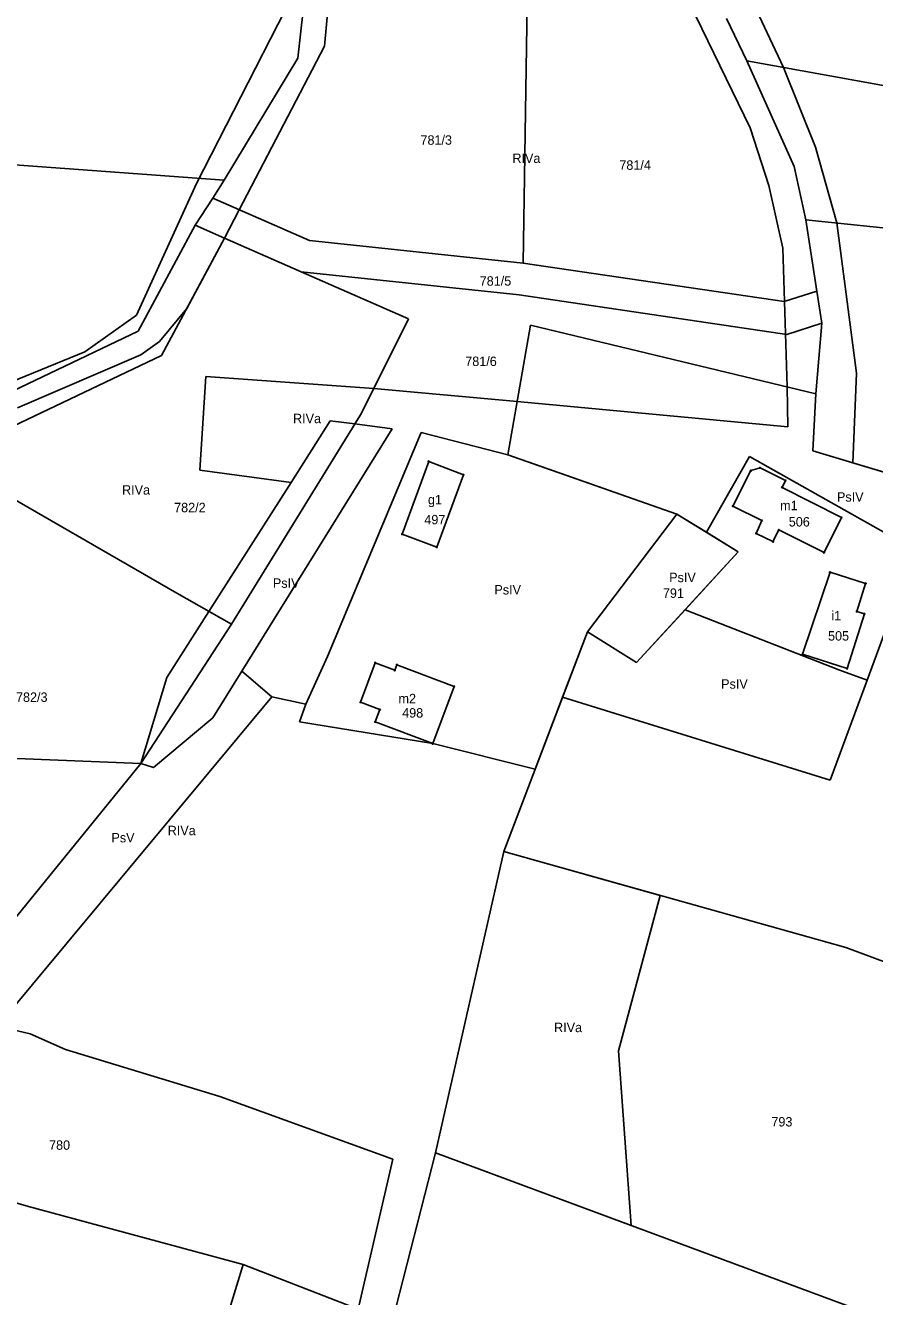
# Model space of a CAD drawing. Extents: x 7498273 to 7499989, y 5499795 to 5500810.
# Drawn here: x 7499281.1 to 7499416.3, y 5500492.7 to 5500695.1 of the extents above; entities that cross this region are included whole.
import ezdxf

# ---------------------------------------------------------------- set-up
doc = ezdxf.new("R2010")
doc.units = 0
for name, color, linetype in [('209-oznaczenie konturu klasyfikacyjnego', 7, 'Continuous'), ('211-numer działki ewidencyjnej', 7, 'Continuous'), ('217-kontur klasyfikacyjny', 7, 'Continuous'), ('218-kontur użytku gruntowego', 7, 'Continuous'), ('219-działka ewidencyjna', 7, 'Continuous'), ('312-budynek ewidencyjny', 7, 'Continuous'), ('312-oznaczenie budynku ewidencyjnego', 7, 'Continuous'), ('312-oznaczenie budynku ewidencyjnego-Atr117', 7, 'Continuous'), ('Punkt budynku', 7, 'Continuous')]:
    doc.layers.add(name, color=color, linetype=linetype)

# ---------------------------------------------------------------- blocks, each defined once
blk = doc.blocks.new('PUNKTBUD')
blk.add_circle((0, 0), 0.09)

msp = doc.modelspace()

# ---------------------------------------------------------------- linework, layer by layer
at = {"layer": '217-kontur klasyfikacyjny'}
for points in [[(7499328.67, 5500691.79), (7499329.52, 5500701.06)], [(7499396.99, 5500698.54), (7499401.78, 5500688.44)], [(7499308.33, 5500669.97), (7499322.43, 5500697.56)], [(7499396.43, 5500678.79), (7499387.8, 5500696.57)], [(7499315.13, 5500665.78), (7499328.67, 5500691.79)], [(7499401.78, 5500688.44), (7499406.83, 5500675.75)], [(7499399.44, 5500669.62), (7499396.43, 5500678.79)], [(7499406.83, 5500675.75), (7499410.25, 5500663.66)], [(7499298.78, 5500648.98), (7499308.33, 5500669.97)], [(7499401.63, 5500659.63), (7499399.44, 5500669.62)], [(7499312.78, 5500661.23), (7499315.13, 5500665.78)], [(7499410.25, 5500663.66), (7499413.39, 5500639.73)], [(7499306.77, 5500650.07), (7499312.78, 5500661.23)], [(7499325, 5500655.88), (7499312.78, 5500661.23)], [(7499402.35, 5500637.55), (7499401.63, 5500659.63)], [(7499342.09, 5500648.38), (7499325, 5500655.88)], [(7499302.41, 5500644.78), (7499306.77, 5500650.07)], [(7499290.56, 5500643.13), (7499298.78, 5500648.98)], [(7499336.54, 5500637.33), (7499342.09, 5500648.38)], [(7499299.44, 5500642.68), (7499302.41, 5500644.78)], [(7499267.15, 5500633.61), (7499290.56, 5500643.13)], [(7499279.82, 5500634.24), (7499299.44, 5500642.68)], [(7499413.39, 5500639.73), (7499412.78, 5500625.5)], [(7499308.83, 5500624.33), (7499309.83, 5500639.23)], [(7499309.83, 5500639.23), (7499336.54, 5500637.33)], [(7499402.44, 5500631.22), (7499402.35, 5500637.55)], [(7499334.43, 5500633.13), (7499336.54, 5500637.33)], [(7499336.54, 5500637.33), (7499359.35, 5500635.23)], [(7499359.35, 5500635.23), (7499402.44, 5500631.22)], [(7499329.61, 5500632.16), (7499323.38, 5500622.35)], [(7499333.52, 5500631.67), (7499329.61, 5500632.16)], [(7499333.52, 5500631.67), (7499334.43, 5500633.13)], [(7499339.48, 5500630.91), (7499333.52, 5500631.67)], [(7499315.52, 5500592.3), (7499339.48, 5500630.91)], [(7499329.16, 5500594.65), (7499344.06, 5500630.33)], [(7499344.06, 5500630.33), (7499357.87, 5500626.74)], [(7499357.87, 5500626.74), (7499364.22, 5500624.51)], [(7499389.5, 5500614.42), (7499396.35, 5500626.47)], [(7499396.35, 5500626.47), (7499422.72, 5500611.61)], [(7499412.78, 5500625.5), (7499426.35, 5500621.42)], [(7499323.38, 5500622.35), (7499308.83, 5500624.33)], [(7499364.22, 5500624.51), (7499384.77, 5500617.29)], [(7499310.3, 5500601.83), (7499323.38, 5500622.35)], [(7499370.57, 5500598.58), (7499384.77, 5500617.29)], [(7499384.77, 5500617.29), (7499389.5, 5500614.42)], [(7499394.54, 5500611.31), (7499389.5, 5500614.42)], [(7499386.1, 5500602.1), (7499394.54, 5500611.31)], [(7499422.72, 5500611.61), (7499415.06, 5500590.87)], [(7499303.6, 5500591.29), (7499310.3, 5500601.83)], [(7499386.1, 5500602.1), (7499378.37, 5500593.67)], [(7499410.58, 5500592.5), (7499386.1, 5500602.1)], [(7499366.6, 5500588.18), (7499370.57, 5500598.58)], [(7499378.37, 5500593.67), (7499370.57, 5500598.58)], [(7499325.71, 5500587.05), (7499329.16, 5500594.65)], [(7499299.48, 5500577.61), (7499303.6, 5500591.29)], [(7499315.52, 5500592.3), (7499310.92, 5500584.9)], [(7499320.32, 5500588.2), (7499315.52, 5500592.3)], [(7499415.06, 5500590.87), (7499409.17, 5500574.93)], [(7499415.06, 5500590.87), (7499410.58, 5500592.5)], [(7499320.32, 5500588.2), (7499276.67, 5500535.79)], [(7499325.71, 5500587.05), (7499320.32, 5500588.2)], [(7499324.71, 5500584.22), (7499325.71, 5500587.05)], [(7499366.6, 5500588.18), (7499362.24, 5500576.7)], [(7499409.17, 5500574.93), (7499366.6, 5500588.18)], [(7499310.92, 5500584.9), (7499301.49, 5500576.99)], [(7499345.92, 5500580.77), (7499324.71, 5500584.22)], [(7499362.24, 5500576.7), (7499345.92, 5500580.77)], [(7499299.48, 5500577.61), (7499253.37, 5500579.46)], [(7499267.24, 5500538), (7499299.48, 5500577.61)], [(7499301.49, 5500576.99), (7499299.48, 5500577.61)], [(7499346.34, 5500515.65), (7499357.23, 5500563.6)], [(7499357.23, 5500563.6), (7499382.14, 5500556.6)], [(7499382.14, 5500556.6), (7499375.51, 5500531.84)], [(7499375.51, 5500531.84), (7499377.52, 5500504.07)], [(7499377.52, 5500504.07), (7499346.34, 5500515.65)]]:
    msp.add_lwpolyline(points, dxfattribs=at)
at = {"layer": '218-kontur użytku gruntowego'}
for points in [[(7499328.67, 5500691.79), (7499329.52, 5500701.06)], [(7499396.99, 5500698.54), (7499401.78, 5500688.44)], [(7499322.43, 5500697.56), (7499308.33, 5500669.97)], [(7499396.43, 5500678.79), (7499387.8, 5500696.57)], [(7499315.13, 5500665.78), (7499328.67, 5500691.79)], [(7499401.78, 5500688.44), (7499406.83, 5500675.75)], [(7499399.44, 5500669.62), (7499396.43, 5500678.79)], [(7499406.83, 5500675.75), (7499410.25, 5500663.66)], [(7499308.33, 5500669.97), (7499298.78, 5500648.98)], [(7499401.63, 5500659.63), (7499399.44, 5500669.62)], [(7499312.78, 5500661.23), (7499315.13, 5500665.78)], [(7499410.25, 5500663.66), (7499413.39, 5500639.73)], [(7499312.78, 5500661.23), (7499306.77, 5500650.07)], [(7499325, 5500655.88), (7499312.78, 5500661.23)], [(7499402.35, 5500637.55), (7499401.63, 5500659.63)], [(7499342.09, 5500648.38), (7499325, 5500655.88)], [(7499306.77, 5500650.07), (7499302.41, 5500644.78)], [(7499298.78, 5500648.98), (7499290.56, 5500643.13)], [(7499336.54, 5500637.33), (7499342.09, 5500648.38)], [(7499302.41, 5500644.78), (7499299.44, 5500642.68)], [(7499290.56, 5500643.13), (7499267.15, 5500633.61)], [(7499299.44, 5500642.68), (7499279.82, 5500634.24)], [(7499413.39, 5500639.73), (7499412.78, 5500625.5)], [(7499308.83, 5500624.33), (7499309.83, 5500639.23)], [(7499309.83, 5500639.23), (7499336.54, 5500637.33)], [(7499402.44, 5500631.22), (7499402.35, 5500637.55)], [(7499334.43, 5500633.13), (7499336.54, 5500637.33)], [(7499336.54, 5500637.33), (7499359.35, 5500635.23)], [(7499359.35, 5500635.23), (7499402.44, 5500631.22)], [(7499329.61, 5500632.16), (7499323.38, 5500622.35)], [(7499333.52, 5500631.67), (7499329.61, 5500632.16)], [(7499333.52, 5500631.67), (7499334.43, 5500633.13)], [(7499339.48, 5500630.91), (7499333.52, 5500631.67)], [(7499315.52, 5500592.3), (7499339.48, 5500630.91)], [(7499329.16, 5500594.65), (7499344.06, 5500630.33)], [(7499344.06, 5500630.33), (7499357.87, 5500626.74)], [(7499357.87, 5500626.74), (7499364.22, 5500624.51)], [(7499389.5, 5500614.42), (7499396.35, 5500626.47)], [(7499396.35, 5500626.47), (7499422.72, 5500611.61)], [(7499412.78, 5500625.5), (7499426.35, 5500621.42)], [(7499323.38, 5500622.35), (7499308.83, 5500624.33)], [(7499364.22, 5500624.51), (7499384.77, 5500617.29)], [(7499323.38, 5500622.35), (7499310.3, 5500601.83)], [(7499370.57, 5500598.58), (7499384.77, 5500617.29)], [(7499384.77, 5500617.29), (7499389.5, 5500614.42)], [(7499394.54, 5500611.31), (7499389.5, 5500614.42)], [(7499386.1, 5500602.1), (7499394.54, 5500611.31)], [(7499422.72, 5500611.61), (7499415.06, 5500590.87)], [(7499310.3, 5500601.83), (7499303.6, 5500591.29)], [(7499386.1, 5500602.1), (7499378.37, 5500593.67)], [(7499410.58, 5500592.5), (7499386.1, 5500602.1)], [(7499366.6, 5500588.18), (7499370.57, 5500598.58)], [(7499378.37, 5500593.67), (7499370.57, 5500598.58)], [(7499325.71, 5500587.05), (7499329.16, 5500594.65)], [(7499303.6, 5500591.29), (7499299.48, 5500577.61)], [(7499310.92, 5500584.9), (7499315.52, 5500592.3)], [(7499320.32, 5500588.2), (7499315.52, 5500592.3)], [(7499415.06, 5500590.87), (7499409.17, 5500574.93)], [(7499415.06, 5500590.87), (7499410.58, 5500592.5)], [(7499276.67, 5500535.79), (7499320.32, 5500588.2)], [(7499325.71, 5500587.05), (7499320.32, 5500588.2)], [(7499324.71, 5500584.22), (7499325.71, 5500587.05)], [(7499366.6, 5500588.18), (7499362.24, 5500576.7)], [(7499409.17, 5500574.93), (7499366.6, 5500588.18)], [(7499301.49, 5500576.99), (7499310.92, 5500584.9)], [(7499345.92, 5500580.77), (7499324.71, 5500584.22)], [(7499362.24, 5500576.7), (7499345.92, 5500580.77)], [(7499253.37, 5500579.46), (7499299.48, 5500577.61)], [(7499299.48, 5500577.61), (7499267.24, 5500538)], [(7499299.48, 5500577.61), (7499301.49, 5500576.99)], [(7499346.34, 5500515.65), (7499357.23, 5500563.6)], [(7499357.23, 5500563.6), (7499382.14, 5500556.6)], [(7499382.14, 5500556.6), (7499375.51, 5500531.84)], [(7499375.51, 5500531.84), (7499377.52, 5500504.07)], [(7499377.52, 5500504.07), (7499346.34, 5500515.65)]]:
    msp.add_lwpolyline(points, dxfattribs=at)
at = {"layer": '219-działka ewidencyjna'}
for points in [[(7499324.46, 5500689.9), (7499325.75, 5500701.37)], [(7499360.33, 5500657.28), (7499360.94, 5500698.54)], [(7499392.68, 5500696.21), (7499395.93, 5500689.5)], [(7499312.74, 5500670.46), (7499324.46, 5500689.9)], [(7499395.93, 5500689.5), (7499469.63, 5500676.18)], [(7499395.93, 5500689.5), (7499403.46, 5500672.64)], [(7499247.45, 5500675.23), (7499312.74, 5500670.46)], [(7499403.46, 5500672.64), (7499405.3, 5500664.18)], [(7499310.9, 5500667.63), (7499312.74, 5500670.46)], [(7499308.1, 5500663.29), (7499310.9, 5500667.63)], [(7499310.9, 5500667.63), (7499326.32, 5500660.87)], [(7499405.3, 5500664.18), (7499407.07, 5500652.82)], [(7499405.3, 5500664.18), (7499422.65, 5500662.34)], [(7499299.03, 5500646.43), (7499308.1, 5500663.29)], [(7499308.1, 5500663.29), (7499312.78, 5500661.23)], [(7499302.73, 5500642.54), (7499312.78, 5500661.23)], [(7499312.78, 5500661.23), (7499325, 5500655.88)], [(7499326.32, 5500660.87), (7499360.33, 5500657.28)], [(7499325, 5500655.88), (7499342.09, 5500648.38)], [(7499325, 5500655.88), (7499359.69, 5500652.21)], [(7499360.33, 5500657.28), (7499401.87, 5500651.14)], [(7499359.69, 5500652.21), (7499402.29, 5500645.91)], [(7499401.87, 5500651.14), (7499407.07, 5500652.82)], [(7499407.07, 5500652.82), (7499407.87, 5500647.72)], [(7499334.43, 5500633.13), (7499342.09, 5500648.38)], [(7499402.29, 5500645.91), (7499407.87, 5500647.72)], [(7499406.93, 5500636.44), (7499407.87, 5500647.72)], [(7499270.84, 5500633.02), (7499299.03, 5500646.43)], [(7499357.87, 5500626.74), (7499361.48, 5500647.42)], [(7499361.48, 5500647.42), (7499406.93, 5500636.44)], [(7499273.54, 5500628.66), (7499302.73, 5500642.54)], [(7499406.42, 5500627.41), (7499406.93, 5500636.44)], [(7499313.88, 5500599.77), (7499334.43, 5500633.13)], [(7499406.42, 5500627.41), (7499474.79, 5500606.86)], [(7499269.39, 5500625.36), (7499305.21, 5500604.75)], [(7499357.87, 5500626.74), (7499384.77, 5500617.29)], [(7499370.57, 5500598.58), (7499384.77, 5500617.29)], [(7499384.77, 5500617.29), (7499394.54, 5500611.31)], [(7499378.37, 5500593.67), (7499394.54, 5500611.31)], [(7499305.21, 5500604.75), (7499313.88, 5500599.77)], [(7499299.48, 5500577.61), (7499313.88, 5500599.77)], [(7499357.23, 5500563.6), (7499370.57, 5500598.58)], [(7499370.57, 5500598.58), (7499378.37, 5500593.67)], [(7499253.37, 5500579.46), (7499299.48, 5500577.61)], [(7499267.24, 5500538), (7499299.48, 5500577.61)], [(7499346.34, 5500515.65), (7499357.23, 5500563.6)], [(7499357.23, 5500563.6), (7499411.68, 5500548.3)], [(7499411.68, 5500548.3), (7499453.32, 5500532.81)], [(7499267.24, 5500538), (7499281.86, 5500534.57)], [(7499281.86, 5500534.57), (7499287.47, 5500532.1)], [(7499287.47, 5500532.1), (7499312.01, 5500524.61)], [(7499312.01, 5500524.61), (7499339.55, 5500514.64)], [(7499239.58, 5500519.27), (7499281.57, 5500507.07)], [(7499334.06, 5500490.73), (7499339.55, 5500514.64)], [(7499339.53, 5500488.89), (7499346.34, 5500515.65)], [(7499346.34, 5500515.65), (7499444.86, 5500479.04)], [(7499281.57, 5500507.07), (7499315.76, 5500497.85)], [(7499304.67, 5500461.68), (7499315.76, 5500497.85)], [(7499315.76, 5500497.85), (7499334.06, 5500490.73)]]:
    msp.add_lwpolyline(points, dxfattribs=at)
at = {"layer": '312-budynek ewidencyjny'}
for points in [[(7499341.05, 5500614.13), (7499345.28, 5500625.69)], [(7499345.28, 5500625.69), (7499350.8, 5500623.57)], [(7499350.8, 5500623.57), (7499346.58, 5500612.05)], [(7499393.69, 5500618.59), (7499396.55, 5500624.24)], [(7499396.55, 5500624.24), (7499398.03, 5500624.68)], [(7499398.03, 5500624.68), (7499402.08, 5500622.67)], [(7499402.08, 5500622.67), (7499401.54, 5500621.57)], [(7499401.54, 5500621.57), (7499411, 5500616.78)], [(7499398.32, 5500616.3), (7499393.69, 5500618.59)], [(7499397.41, 5500614.24), (7499398.32, 5500616.3)], [(7499411, 5500616.78), (7499408.21, 5500611.2)], [(7499346.58, 5500612.05), (7499341.05, 5500614.13)], [(7499400.08, 5500612.93), (7499397.41, 5500614.24)], [(7499401, 5500614.79), (7499400.08, 5500612.93)], [(7499408.21, 5500611.2), (7499401, 5500614.79)], [(7499404.77, 5500594.99), (7499409.17, 5500608.05)], [(7499409.17, 5500608.05), (7499414.83, 5500606.27)], [(7499414.83, 5500606.27), (7499413.43, 5500601.8)], [(7499414.63, 5500601.42), (7499411.9, 5500592.74)], [(7499413.43, 5500601.8), (7499414.63, 5500601.42)], [(7499411.9, 5500592.74), (7499404.77, 5500594.99)], [(7499334.42, 5500587.36), (7499336.77, 5500593.63)], [(7499336.77, 5500593.63), (7499339.88, 5500592.45)], [(7499339.88, 5500592.45), (7499340.21, 5500593.31)], [(7499340.21, 5500593.31), (7499349.35, 5500589.86)], [(7499349.35, 5500589.86), (7499345.92, 5500580.77)], [(7499337.5, 5500586.19), (7499334.42, 5500587.36)], [(7499336.76, 5500584.23), (7499337.5, 5500586.19)], [(7499345.92, 5500580.77), (7499336.76, 5500584.23)]]:
    msp.add_lwpolyline(points, dxfattribs=at)

# ---------------------------------------------------------------- block references
at = {"layer": 'Punkt budynku'}
for p in [(7499345.28, 5500625.69), (7499350.8, 5500623.57), (7499396.55, 5500624.24), (7499398.03, 5500624.68), (7499401.54, 5500621.57), (7499402.08, 5500622.67), (7499393.69, 5500618.59), (7499398.32, 5500616.3), (7499411, 5500616.78), (7499341.05, 5500614.13), (7499397.41, 5500614.24), (7499401, 5500614.79), (7499346.58, 5500612.05), (7499400.08, 5500612.93), (7499408.21, 5500611.2), (7499409.17, 5500608.05), (7499414.83, 5500606.27), (7499413.43, 5500601.8), (7499414.63, 5500601.42), (7499404.77, 5500594.99), (7499336.77, 5500593.63), (7499340.21, 5500593.31), (7499339.88, 5500592.45), (7499411.9, 5500592.74), (7499349.35, 5500589.86), (7499334.42, 5500587.36), (7499337.5, 5500586.19), (7499336.76, 5500584.23), (7499345.92, 5500580.77)]:
    msp.add_blockref('PUNKTBUD', p, dxfattribs=at)

# ---------------------------------------------------------------- texts
at = {"layer": '209-oznaczenie konturu klasyfikacyjnego'}
for s, p in [('RIVa', (7499358.61, 5500673.22)), ('RIVa', (7499323.69, 5500631.79)), ('RIVa', (7499296.47, 5500620.42)), ('PsIV', (7499410.27, 5500619.3)), ('PsIV', (7499320.48, 5500605.58)), ('PsIV', (7499383.56, 5500606.48)), ('PsIV', (7499355.74, 5500604.52)), ('PsIV', (7499391.83, 5500589.52)), ('RIVa', (7499303.74, 5500566.19)), ('PsV', (7499294.78, 5500565.05)), ('RIVa', (7499365.24, 5500534.84))]:
    msp.add_text(s, height=1.5, dxfattribs=at).set_placement(p)
at = {"layer": '211-numer działki ewidencyjnej'}
for s, p in [('781/3', (7499343.97, 5500676.12)), ('781/4', (7499375.63, 5500672.13)), ('781/5', (7499353.4, 5500653.68)), ('781/6', (7499351.1, 5500640.89)), ('782/2', (7499304.76, 5500617.61)), ('791', (7499382.56, 5500603.98)), ('782/3', (7499279.59, 5500587.42)), ('793', (7499399.83, 5500519.82)), ('780', (7499284.85, 5500516.11))]:
    msp.add_text(s, height=1.5, dxfattribs=at).set_placement(p)
at = {"layer": '312-oznaczenie budynku ewidencyjnego'}
for s, p in [('497', (7499344.59, 5500615.69)), ('506', (7499402.6, 5500615.34)), ('505', (7499408.85, 5500597.18)), ('498', (7499341.06, 5500584.92))]:
    msp.add_text(s, height=1.5, dxfattribs=at).set_placement(p)
at = {"layer": '312-oznaczenie budynku ewidencyjnego-Atr117'}
for s, p in [('g1', (7499345.159, 5500618.87)), ('m1', (7499401.225, 5500617.94)), ('i1', (7499409.382, 5500600.4)), ('m2', (7499340.476, 5500587.2))]:
    msp.add_text(s, height=1.5, dxfattribs=at).set_placement(p)

doc.saveas('drawing.dxf')
